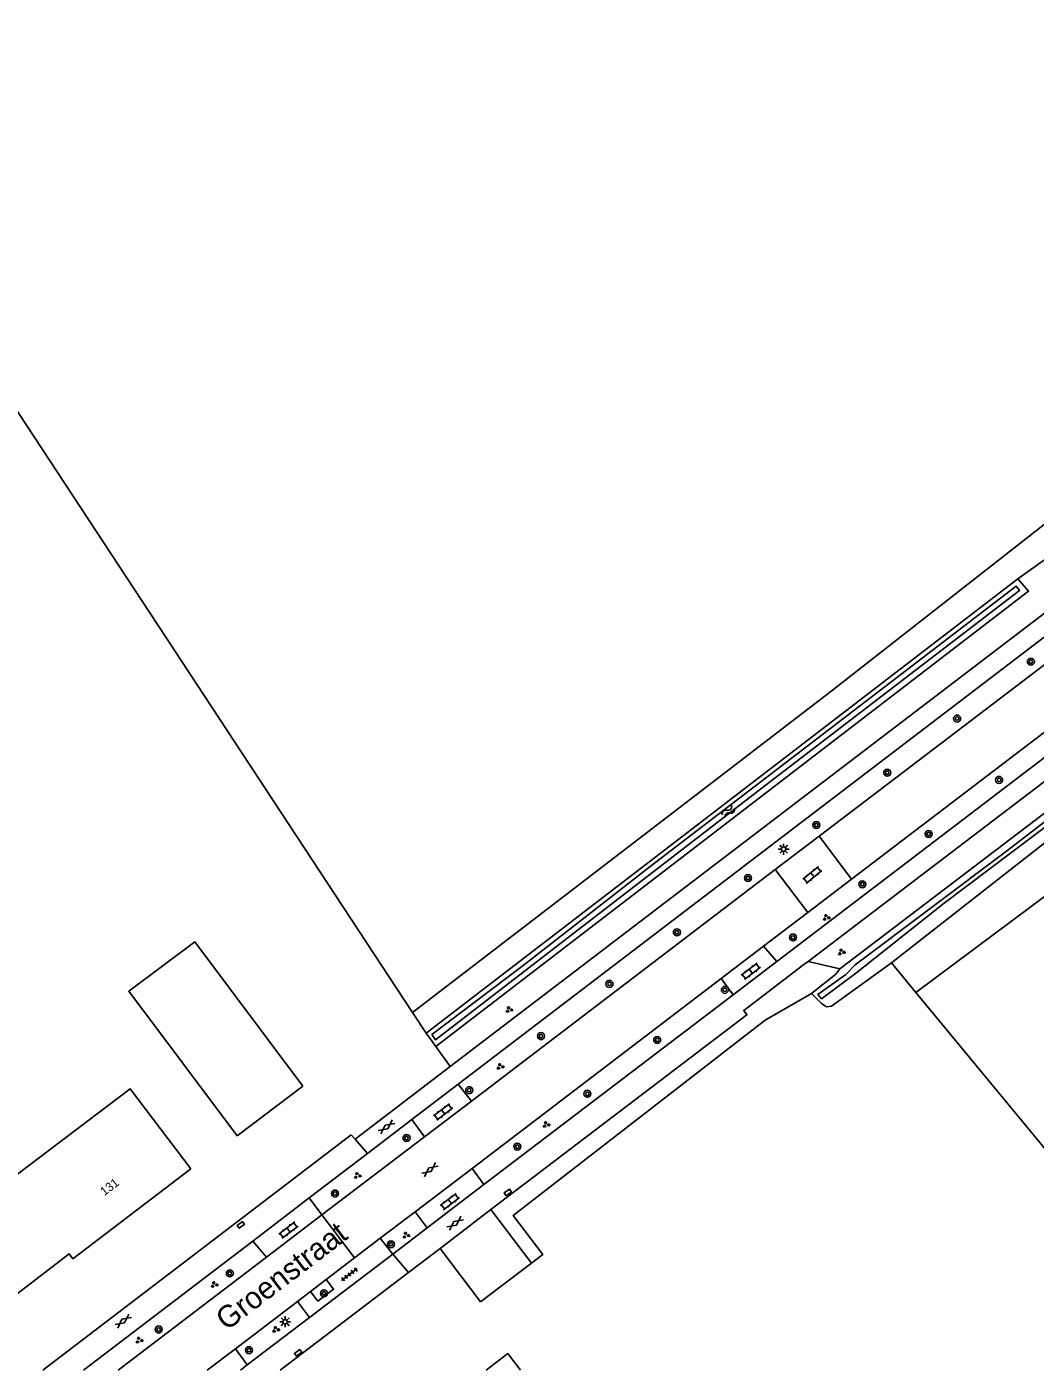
# Model space of a CAD drawing. Extents: x 137000 to 140001, y 403500 to 406000.
# Drawn here: x 138983.6 to 139098.9, y 403500 to 403653.5 of the extents above; entities that cross this region are included whole.
import ezdxf

# ---------------------------------------------------------------- set-up
doc = ezdxf.new("R2010")
doc.units = 0
for name, color, linetype in [('gg-afsc-draadraster', 7, 'Continuous'), ('gg-afsc-hekwerk', 7, 'Continuous'), ('gg-afsc-lijn draadraster', 7, 'Continuous'), ('gg-anno-huisnummerreeks BGT', 7, 'Continuous'), ('gg-anno-openbare ruimte label', 7, 'Continuous'), ('gg-bbg-bijgebouw', 7, 'Continuous'), ('gg-bbg-gedigitaliseerde bebouwing', 7, 'Continuous'), ('gg-bbg-gedigitaliseerde bijgebouw', 7, 'Continuous'), ('gg-bbg-hoofdgebouw', 7, 'Continuous'), ('gg-knt-bronhoudergrens', 7, 'Continuous'), ('gg-knt-verharding', 7, 'Continuous'), ('gg-kntw-bovenkant insteek waterloop', 7, 'Continuous'), ('gg-kntw-waterlijn', 7, 'Continuous'), ('gt-grn-groengrens', 7, 'Continuous'), ('gt-grn-groengrens NZ', 7, 'Continuous'), ('gt-grn-vlakafsluiter', 7, 'Continuous'), ('gt-grn-weggrens', 7, 'Continuous'), ('gt-symb-boom', 7, 'Continuous'), ('gt-symb-gesloten verharding', 7, 'Continuous'), ('gt-symb-groenvak', 7, 'Continuous'), ('gt-symb-klinker verharding', 7, 'Continuous'), ('gt-symb-kolk', 7, 'Continuous'), ('gt-symb-lichtmast', 7, 'Continuous'), ('gt-symb-tegel verharding', 7, 'Continuous'), ('gt-symb-watersymbool', 7, 'Continuous')]:
    doc.layers.add(name, color=color, linetype=linetype)

# ---------------------------------------------------------------- blocks, each defined once
blk = doc.blocks.new('gt0-BOOM')
at = {"layer": 'gt-symb-boom'}
for radius in [0.4, 0.2]:
    blk.add_circle((0, 0), radius, dxfattribs=at)
blk = doc.blocks.new('gt0-GRVAK')
at = {"layer": 'gt-symb-groenvak'}
for p, q in [((-0.11, 0.19), (-0.23, 0.24)), ((-0.18, 0.15), (0.09, 0.15)), ((-0.09, 0.21), (-0.16, 0.32)), ((-0.05, 0.21), (-0.05, 0.39)), ((0, 0.21), (0.06, 0.32)), ((0.01, 0.19), (0.13, 0.24)), ((0.26, -0.05), (0.2, 0.06)), ((0.3, -0.05), (0.3, 0.13)), ((0.35, -0.05), (0.41, 0.06)), ((-0.24, -0.23), (-0.36, -0.18)), ((-0.32, -0.26), (-0.05, -0.26)), ((-0.23, -0.21), (-0.29, -0.09)), ((-0.18, -0.2), (-0.18, -0.02)), ((-0.14, -0.21), (-0.07, -0.09)), ((-0.12, -0.23), (0, -0.18)), ((0.24, -0.07), (0.12, -0.02)), ((0.17, -0.11), (0.44, -0.11)), ((0.37, -0.07), (0.49, -0.02))]:
    blk.add_line(p, q, dxfattribs=at)
blk = doc.blocks.new('gt0-KL1')
at = {"layer": 'gt-symb-klinker verharding'}
for p, q in [((-1.15, 0.3), (1.15, 0.3)), ((-1, -0.3), (-1, 0.3)), ((-0.5, 0.3), (-0.5, 0.45)), ((0, -0.3), (0, 0.3)), ((0.5, 0.3), (0.5, 0.45)), ((1, -0.3), (1, 0.3)), ((-1.15, -0.3), (1.15, -0.3)), ((-0.5, -0.45), (-0.5, -0.3)), ((0.5, -0.45), (0.5, -0.3))]:
    blk.add_line(p, q, dxfattribs=at)
blk = doc.blocks.new('gt0-TEG1')
at = {"layer": 'gt-symb-tegel verharding'}
for p, q in [((-1.12, 0), (1.12, 0)), ((-0.9, -0.25), (-0.9, 0.25)), ((-0.45, -0.25), (-0.45, 0.25)), ((0, -0.25), (0, 0.25)), ((0.45, -0.25), (0.45, 0.25)), ((0.9, -0.25), (0.9, 0.25))]:
    blk.add_line(p, q, dxfattribs=at)
blk = doc.blocks.new('gt0-KOLK')
at = {"layer": 'gt-symb-kolk'}
blk.add_lwpolyline([(0, 0), (0.37, 0), (0.37, 0.4), (-0.38, 0.4), (-0.38, 0), (0, 0)], dxfattribs=at)
blk = doc.blocks.new('gt0-GESVH1')
at = {"layer": 'gt-symb-gesloten verharding'}
for p, q in [((-0.99, -0.26), (0.01, 0.24)), ((0.01, -0.26), (-0.99, 0.24)), ((0.01, 0.24), (1.01, -0.26)), ((1.01, 0.24), (0.01, -0.26))]:
    blk.add_line(p, q, dxfattribs=at)
blk = doc.blocks.new('gt0-LMAST')
at = {"layer": 'gt-symb-lichtmast'}
for p, q in [((-0.18, 0.17), (-0.45, 0.44)), ((-0.01, 0.25), (-0.01, 0.62)), ((0.17, 0.17), (0.44, 0.44)), ((-0.26, 0), (-0.63, 0)), ((-0.18, -0.18), (-0.45, -0.45)), ((-0.01, -0.25), (-0.01, -0.63)), ((0.44, -0.45), (0.17, -0.18)), ((0.24, 0), (0.62, 0))]:
    blk.add_line(p, q, dxfattribs=at)
blk.add_circle((-0.01, 0), 0.25, dxfattribs=at)
blk = doc.blocks.new('gt0-WA')
at = {"layer": 'gt-symb-watersymbool'}
for centre, start, end in [((-0.32, 0.02), 28.0725, 151.9275), ((0.43, 0.42), 208.0725, 331.9275), ((-0.32, -0.43), 28.0725, 151.9275), ((0.43, -0.03), 208.0725, 331.9275)]:
    blk.add_arc(centre, 0.425, start, end, dxfattribs=at)

msp = doc.modelspace()

# ---------------------------------------------------------------- linework, layer by layer
at = {"layer": 'gg-afsc-draadraster'}
msp.add_line((139029.24, 403538.51), (139027.68, 403540.89), dxfattribs=at)
msp.add_lwpolyline([(139027.68, 403540.89), (138979.09, 403614.68), (138954.71, 403653.54)], dxfattribs=at)
at = {"layer": 'gg-afsc-hekwerk'}
msp.add_line((139035.47, 403507.82), (139041.31, 403512.24), dxfattribs=at)
msp.add_lwpolyline([(139068.03, 403540), (139039.21, 403517.69), (139042.6, 403513.23), (139041.31, 403512.24)], dxfattribs=at)
at = {"layer": 'gg-afsc-lijn draadraster'}
msp.add_line((139029.24, 403538.51), (139027.68, 403540.89), dxfattribs=at)
msp.add_lwpolyline([(139027.68, 403540.89), (138979.09, 403614.68), (138954.71, 403653.54)], dxfattribs=at)
at = {"layer": 'gg-bbg-bijgebouw'}
msp.add_line((139007.61, 403526.79), (139015.12, 403532.47), dxfattribs=at)
at = {"layer": 'gg-bbg-gedigitaliseerde bebouwing'}
msp.add_line((139038.59, 403501.9), (139040.04, 403500), dxfattribs=at)
msp.add_lwpolyline([(139002.34, 403523.02), (138995.4, 403532.17), (138973.35, 403515.51), (138979.95, 403506.83)], dxfattribs=at)
at = {"layer": 'gg-bbg-gedigitaliseerde bijgebouw'}
msp.add_lwpolyline([(139007.61, 403526.79), (138995.25, 403543.3), (139002.79, 403548.94), (139015.12, 403532.47)], dxfattribs=at)
at = {"layer": 'gg-bbg-hoofdgebouw'}
msp.add_line((139036.1, 403500), (139038.59, 403501.9), dxfattribs=at)
msp.add_lwpolyline([(138979.95, 403506.83), (138988.4, 403513.3), (138988.83, 403512.74), (139002.34, 403523.02)], dxfattribs=at)
at = {"layer": 'gg-knt-bronhoudergrens'}
for points in [[(139160.51, 403644.06), (139075.52, 403577.58), (139027.68, 403540.89)], [(139137.23, 403582.45), (139129.64, 403576.24), (139085.24, 403543.18)], [(139085.24, 403543.18), (139099.78, 403525.61), (139117.74, 403502.37), (139119.33, 403500)]]:
    msp.add_lwpolyline(points, dxfattribs=at)
at = {"layer": 'gg-knt-verharding'}
for p, q in [((139031.98, 403534.69), (139175.19, 403643.9)), ((139184.62, 403631.79), (139072.93, 403546.71)), ((139128.4, 403594.57), (139077.91, 403556.12)), ((139069.34, 403546.71), (139129.77, 403592.72)), ((139100.44, 403584.15), (139032.91, 403532.67)), ((139074.18, 403561.03), (139101.94, 403582.16)), ((139069.18, 403557.22), (139074.18, 403561.03)), ((139074.18, 403561.03), (139077.91, 403556.12)), ((139034.42, 403530.76), (139069.18, 403557.22)), ((139069.18, 403557.22), (139072.91, 403552.32)), ((139077.91, 403556.12), (139072.91, 403552.32)), ((139072.91, 403552.32), (139067.84, 403548.45)), ((139067.84, 403548.45), (139062.98, 403544.75)), ((139069.34, 403546.71), (139067.84, 403548.45)), ((139064.36, 403542.91), (139069.34, 403546.71)), ((139062.98, 403544.75), (139034.49, 403523.06)), ((139062.98, 403544.75), (139064.36, 403542.91)), ((139035.85, 403521.21), (139064.36, 403542.91)), ((139021.12, 403526.41), (139031.98, 403534.69)), ((139032.91, 403532.67), (139027.61, 403528.63)), ((139032.91, 403532.67), (139034.42, 403530.76)), ((139029.05, 403526.67), (139034.42, 403530.76)), ((139027.61, 403528.63), (139022.54, 403524.76)), ((139029.05, 403526.67), (139027.61, 403528.63)), ((138985.4, 403500), (139020.68, 403526.91)), ((139017.31, 403517.74), (139029.05, 403526.67)), ((139020.68, 403526.91), (139021.12, 403526.41)), ((139022.54, 403524.76), (139015.87, 403519.68)), ((139034.49, 403523.06), (139027.98, 403518.1)), ((139035.85, 403521.21), (139034.49, 403523.06)), ((139029.35, 403516.26), (139035.85, 403521.21)), ((139015.87, 403519.68), (139009.42, 403514.76)), ((139017.31, 403517.74), (139015.87, 403519.68)), ((139010.99, 403512.93), (139017.31, 403517.74)), ((139027.98, 403518.1), (139023.99, 403515.07)), ((139027.98, 403518.1), (139029.35, 403516.26)), ((139036.66, 403518.35), (139030.83, 403513.92)), ((139036.66, 403518.35), (139041.31, 403512.24)), ((139025.42, 403513.27), (139029.35, 403516.26)), ((138990.06, 403500), (139009.42, 403514.76)), ((139009.42, 403514.76), (139010.99, 403512.93)), ((139023.99, 403515.07), (139021.05, 403512.83)), ((139023.99, 403515.07), (139025.42, 403513.27)), ((138994.01, 403500), (139010.99, 403512.93)), ((139015.9, 403506.02), (139025.42, 403513.27)), ((139021.05, 403512.83), (139017.81, 403510.36)), ((139030.83, 403513.92), (139027.22, 403511.17)), ((139035.47, 403507.82), (139030.83, 403513.92)), ((139012.54, 403500), (139027.22, 403511.17)), ((139017.81, 403510.36), (139016.02, 403509)), ((139016.02, 403509), (139014.52, 403507.86)), ((139014.52, 403507.86), (139007.42, 403502.45)), ((139014.52, 403507.86), (139015.9, 403506.02)), ((139008.77, 403500.59), (139015.9, 403506.02)), ((139004.2, 403500), (139007.42, 403502.45)), ((139007.42, 403502.45), (139008.77, 403500.59)), ((139007.99, 403500), (139008.77, 403500.59))]:
    msp.add_line(p, q, dxfattribs=at)
for points in [[(139072.93, 403546.71), (139072.45, 403546.35), (139065.57, 403541.11), (139065.93, 403540.61), (139036.66, 403518.35)], [(139016.02, 403509), (139016.86, 403507.89), (139018.65, 403509.25), (139017.81, 403510.36)]]:
    msp.add_lwpolyline(points, dxfattribs=at)
at = {"layer": 'gg-kntw-bovenkant insteek waterloop'}
for p, q in [((139096.93, 403590.45), (139029.24, 403538.51)), ((139133.87, 403589.48), (139076.56, 403545.87)), ((139029.24, 403538.51), (139030.36, 403537.01))]:
    msp.add_line(p, q, dxfattribs=at)
for points in [[(139096.93, 403590.45), (139098.15, 403589.04), (139030.36, 403537.01)], [(139133.63, 403586.48), (139117.98, 403574.33), (139082.47, 403546.54)], [(139082.47, 403546.54), (139075.61, 403541.59), (139075.04, 403541.53), (139074.47, 403541.92), (139073.32, 403543.07)], [(139073.32, 403543.07), (139076.1, 403545.28), (139076.56, 403545.87)]]:
    msp.add_lwpolyline(points, dxfattribs=at)
at = {"layer": 'gg-kntw-waterlijn'}
for points in [[(139029.91, 403538.36), (139040.33, 403546.26), (139054.86, 403557.58), (139096.72, 403589.63), (139097.11, 403589.11), (139068.18, 403566.96), (139030.3, 403537.76), (139029.91, 403538.36)], [(139135, 403588.2), (139134.02, 403588.89), (139095.77, 403559.44), (139078.3, 403546.34), (139077.25, 403545.24), (139074.03, 403542.92), (139074.46, 403542.46), (139078.34, 403545.35), (139088.49, 403553.38), (139109.25, 403569.01), (139133.18, 403587.36), (139133.79, 403587.21)]]:
    msp.add_lwpolyline(points, dxfattribs=at)
at = {"layer": 'gt-grn-groengrens'}
for p, q in [((139102.75, 403594.62), (139096.93, 403590.45)), ((139068.03, 403540), (139073.32, 403543.07)), ((139030.36, 403537.01), (139031.98, 403534.69))]:
    msp.add_line(p, q, dxfattribs=at)
at = {"layer": 'gt-grn-groengrens NZ'}
msp.add_line((139076.56, 403545.87), (139072.93, 403546.71), dxfattribs=at)
at = {"layer": 'gt-grn-vlakafsluiter'}
msp.add_line((139085.24, 403543.18), (139082.47, 403546.54), dxfattribs=at)
at = {"layer": 'gt-grn-weggrens'}
for p, q in [((139021.12, 403526.41), (139022.54, 403524.76)), ((139017.31, 403517.74), (139021.05, 403512.83)), ((139027.22, 403511.17), (139025.42, 403513.27))]:
    msp.add_line(p, q, dxfattribs=at)

# ---------------------------------------------------------------- block references
at = {"layer": 'gt-symb-boom'}
for p in [(139098.41, 403580.98), (139089.98, 403574.48), (139081.98, 403568.29), (139094.78, 403567.47), (139073.87, 403562.31), (139086.72, 403561.28), (139066.06, 403556.25), (139079.13, 403555.54), (139057.92, 403550.04), (139071.21, 403549.46), (139050.21, 403544.15), (139063.41, 403543.47), (139042.37, 403538.18), (139055.67, 403537.73), (139034.17, 403532), (139047.69, 403531.59), (139027, 403526.54), (139039.67, 403525.55), (139018.81, 403520.19), (139025.22, 403514.39), (139006.79, 403511.07), (139017.55, 403508.77), (138998.65, 403504.65), (139008.99, 403502.28)]:
    msp.add_blockref('gt0-BOOM', p, dxfattribs=at)
at = {"layer": 'gt-symb-gesloten verharding'}
for p, rotation in [((139024.69, 403527.8), 37.282255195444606), ((139029.67, 403522.92), 37.28225519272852), ((139032.54, 403516.79), 37.28225519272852), ((138994.59, 403505.61), 37.282255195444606)]:
    msp.add_blockref('gt0-GESVH1', p, dxfattribs=dict(at, rotation=rotation))
at = {"layer": 'gt-symb-groenvak'}
for p in [(139075.01, 403551.74), (139076.74, 403547.78), (139038.72, 403541.2), (139037.7, 403534.71), (139042.96, 403528.06), (139021.37, 403522.24), (139026.93, 403515.42), (139005, 403509.77), (139012.04, 403504.65), (138996.41, 403503.41)]:
    msp.add_blockref('gt0-GRVAK', p, dxfattribs=at)
at = {"layer": 'gt-symb-klinker verharding'}
for p, rotation in [((139073.42, 403556.6), 39.4022412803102), ((139066.38, 403545.59), 37.030389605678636), ((139031.19, 403529.51), 37.28225519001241), ((139031.95, 403519.27), 37.28225519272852), ((139013.49, 403516.01), 37.28225519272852)]:
    msp.add_blockref('gt0-KL1', p, dxfattribs=dict(at, rotation=rotation))
at = {"layer": 'gt-symb-kolk'}
for p, rotation in [((139038.71, 403520.16), 37.282255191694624), ((139008.17, 403516.44), 37.28225519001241), ((139014.73, 403501.82), 37.28225519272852)]:
    msp.add_blockref('gt0-KOLK', p, dxfattribs=dict(at, rotation=rotation))
at = {"layer": 'gt-symb-lichtmast'}
for p in [(139070.14, 403559.55), (139013.12, 403505.53)]:
    msp.add_blockref('gt0-LMAST', p, dxfattribs=at)
at = {"layer": 'gt-symb-tegel verharding', "rotation": 37.28225519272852}
msp.add_blockref('gt0-TEG1', (139020.47, 403510.94), dxfattribs=at)
at = {"layer": 'gt-symb-watersymbool', "rotation": 45.16208097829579}
msp.add_blockref('gt0-WA', (139063.77, 403563.81), dxfattribs=at)

# ---------------------------------------------------------------- texts
at = {"layer": 'gg-anno-huisnummerreeks BGT'}
msp.add_text('131', height=1, rotation=37.2, dxfattribs=at).set_placement((138992.43, 403519.88))
at = {"layer": 'gg-anno-openbare ruimte label'}
msp.add_text('Groenstraat', height=2.5, rotation=37.3, dxfattribs=at).set_placement((139006.41, 403504.43))

doc.saveas('drawing.dxf')
